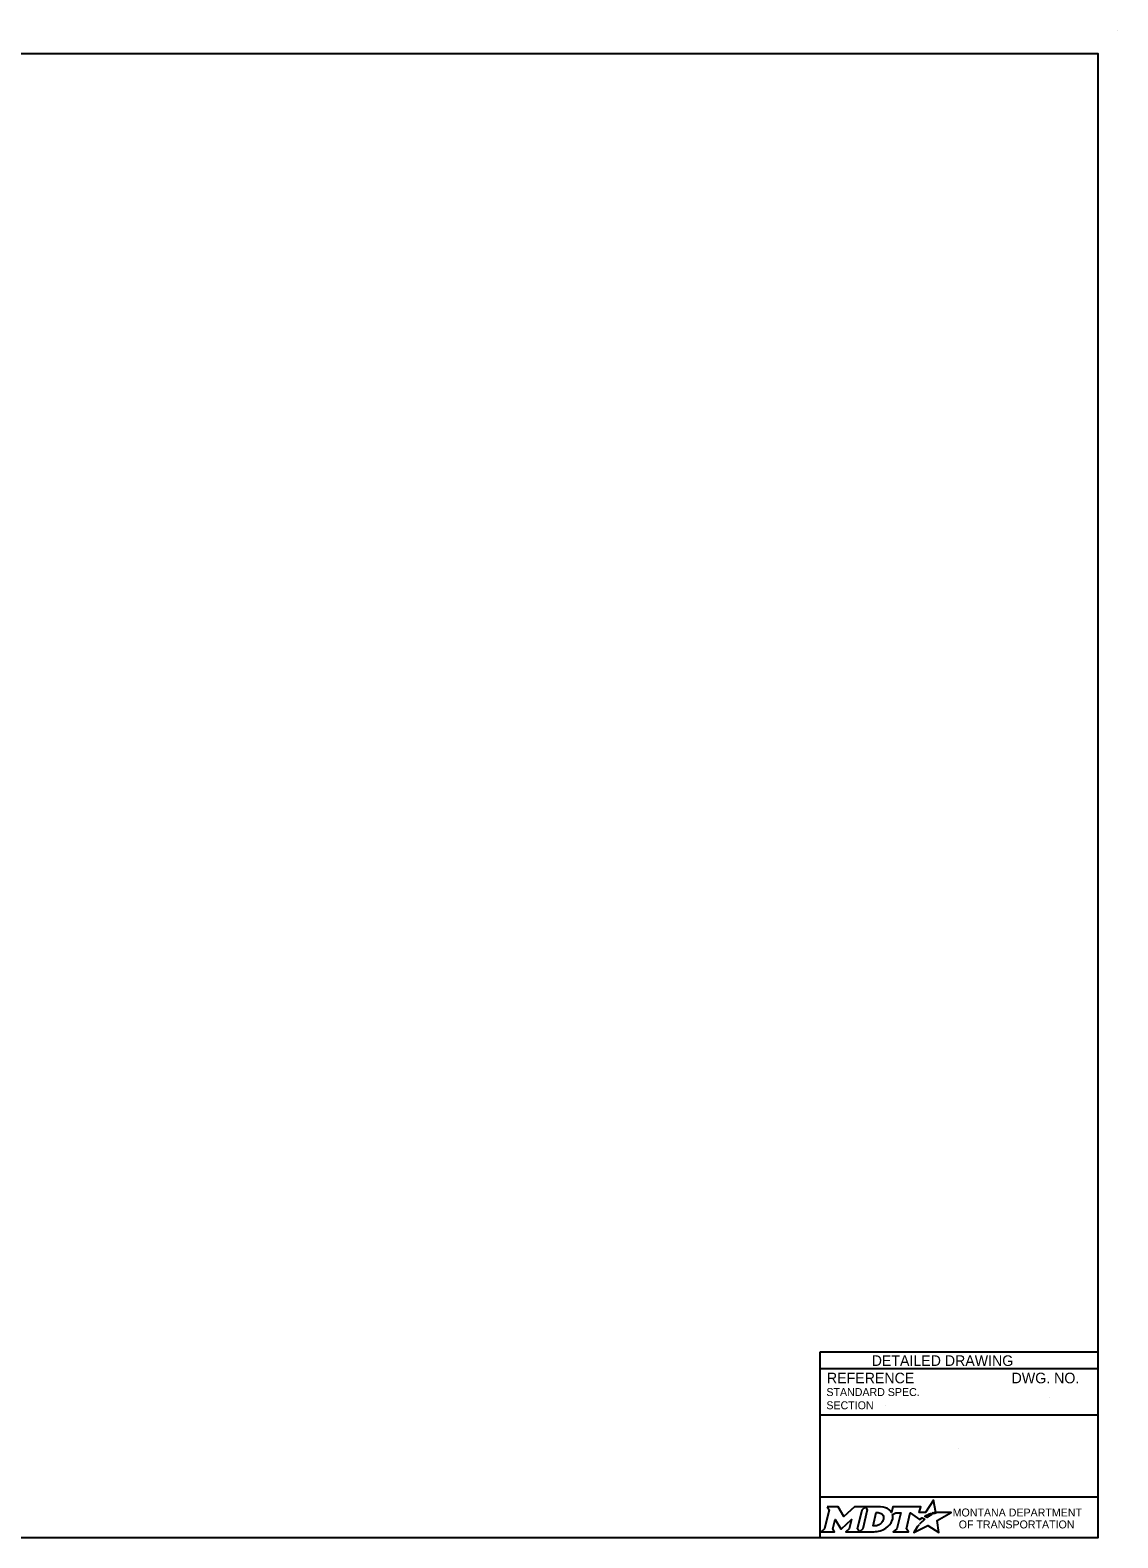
# Model space of a CAD drawing. Extents: x 49991.4 to 50044.5, y 49987.6 to 50011.4.
# Drawn here: x 50008.69 to 50016.9, y 49987.8 to 49999.18 of the extents above; entities that cross this region are included whole.
import ezdxf

# ---------------------------------------------------------------- set-up
doc = ezdxf.new("R2010")
doc.units = 0
for name, color, linetype in [('Default', 7, 'Continuous'), ('Level 1', 7, 'Continuous'), ('Level 5', 7, 'Continuous')]:
    doc.layers.add(name, color=color, linetype=linetype)

msp = doc.modelspace()

# ---------------------------------------------------------------- linework, layer by layer
at = {"layer": 'Default'}
for points in [[(50015.513, 49987.981), (50015.502, 49987.987), (50015.514, 49987.99), (50015.526, 49987.991), (50015.508, 49988.082), (50015.449, 49987.99), (50015.401, 49987.99), (50015.412, 49988.034), (50015.202, 49988.034), (50015.192, 49987.991), (50015.186, 49988)], [(50014.706, 49988.034), (50014.72, 49988.01), (50014.686, 49987.867), (50014.66, 49987.845), (50014.762, 49987.845), (50014.749, 49987.867), (50014.765, 49987.937), (50014.809, 49987.868), (50014.814, 49987.868), (50014.889, 49987.938), (50014.872, 49987.867), (50014.848, 49987.845), (50014.949, 49987.845), (50014.936, 49987.868), (50014.969, 49988.011)], [(50014.969, 49988.011), (50014.994, 49988.034), (50014.912, 49988.034), (50014.832, 49987.961), (50014.788, 49988.034), (50014.706, 49988.034)], [(50015.108, 49988.034), (50014.994, 49988.034), (50015.009, 49988.011), (50014.975, 49987.867), (50014.949, 49987.845), (50015.06, 49987.845)], [(50015.132, 49987.947), (50015.13, 49987.939), (50015.127, 49987.93), (50015.123, 49987.922), (50015.118, 49987.914), (50015.111, 49987.907), (50015.103, 49987.901), (50015.095, 49987.896), (50015.086, 49987.892), (50015.077, 49987.89), (50015.067, 49987.889), (50015.052, 49987.889), (50015.075, 49987.989), (50015.091, 49987.989), (50015.099, 49987.988), (50015.106, 49987.986), (50015.113, 49987.983), (50015.119, 49987.979), (50015.124, 49987.974), (50015.128, 49987.968), (50015.13, 49987.962), (50015.132, 49987.955), (50015.132, 49987.952), (50015.132, 49987.947)], [(50015.199, 49987.975), (50015.224, 49987.988), (50015.261, 49987.988), (50015.232, 49987.867), (50015.205, 49987.845), (50015.321, 49987.845), (50015.304, 49987.867), (50015.332, 49987.988), (50015.403, 49987.936), (50015.424, 49987.951), (50015.444, 49987.94)], [(50015.388, 49987.884), (50015.373, 49987.86), (50015.368, 49987.852), (50015.362, 49987.844), (50015.36, 49987.839), (50015.465, 49987.893), (50015.549, 49987.838), (50015.536, 49987.93), (50015.643, 49987.989), (50015.594, 49987.989), (50015.564, 49987.99), (50015.543, 49987.99), (50015.536, 49987.989), (50015.531, 49987.987), (50015.523, 49987.985), (50015.513, 49987.981)], [(50015.462, 49987.954), (50015.46, 49987.952), (50015.442, 49987.961), (50015.452, 49987.967), (50015.456, 49987.969), (50015.465, 49987.973), (50015.47, 49987.976), (50015.478, 49987.979), (50015.485, 49987.982), (50015.497, 49987.974), (50015.493, 49987.972), (50015.489, 49987.97), (50015.484, 49987.967), (50015.479, 49987.965), (50015.478, 49987.963), (50015.475, 49987.962), (50015.472, 49987.96), (50015.47, 49987.959), (50015.467, 49987.957), (50015.465, 49987.955), (50015.462, 49987.954)], [(50015.106, 49987.852), (50015.114, 49987.855), (50015.127, 49987.86), (50015.148, 49987.871)], [(50015.402, 49987.9), (50015.402, 49987.9)]]:
    msp.add_lwpolyline(points, dxfattribs=at)
for centre, radius, start, end in [((50015.087, 49987.973), 0.118, 300.9103, 339.1383), ((50015.131, 49987.955), 0.0709, 339.5329, 15.8582)]:
    msp.add_arc(centre, radius, start, end, dxfattribs=at)
for centre, major_axis, ratio, start_param, end_param in [((50015.106, 49987.986), (0.0834, -0.0037), 0.568097, 0.61298, 1.570796), ((50015.161, 49987.994), (0.0361, -0.0295), 0.469099, 1.225588, 1.570796), ((50015.433, 49987.93), (-0.0112, -0.0097), 0.021651, 3.157348, 6.283185), ((50015.06, 49987.993), (0, 0.148), 0.987302, 3.139398, 3.456847), ((50015.395, 49987.892), (-0.00694, -0.00806), 0.008222, 0, 3.137361), ((50015.412, 49987.911), (-0.0098, -0.0102), 0.016458, 3.141593, 6.279097)]:
    msp.add_ellipse(centre, major_axis=major_axis, ratio=ratio, start_param=start_param, end_param=end_param, dxfattribs=at)
at = {"layer": 'Level 1'}
msp.add_line((50016.9, 49999.176), (50016.9, 49999.176), dxfattribs=at)
msp.add_lwpolyline([(49999.384, 49998.999), (50016.75, 49998.999), (50016.75, 49987.799), (49999.384, 49987.799)], close=True, dxfattribs=at)
at = {"layer": 'Level 5'}
for p, q in [((50016.75, 49989.199), (50014.65, 49989.199)), ((50014.65, 49989.199), (50014.65, 49987.799)), ((50016.75, 49989.074), (50014.65, 49989.074)), ((50016.386, 49988.859), (50016.386, 49988.859)), ((50016.75, 49988.724), (50014.65, 49988.724)), ((50015.144, 49988.799), (50015.144, 49988.799)), ((50015.7, 49988.475), (50015.7, 49988.475)), ((50016.75, 49988.106), (50014.65, 49988.106))]:
    msp.add_line(p, q, dxfattribs=at)

# ---------------------------------------------------------------- texts
at = {"layer": 'Default'}
for s, p in [('MONTANA DEPARTMENT', (50015.653, 49987.96)), ('OF TRANSPORTATION', (50015.699, 49987.87))]:
    msp.add_text(s, height=0.06, rotation=360, dxfattribs=at).set_placement(p)
at = {"layer": 'Level 5'}
for s, height, p in [('DETAILED DRAWING', 0.0799, (50015.042, 49989.096)), ('REFERENCE', 0.08, (50014.704, 49988.965)), ('DWG. NO.', 0.08, (50016.098, 49988.965)), ('STANDARD SPEC.', 0.06, (50014.7, 49988.869)), ('SECTION', 0.06, (50014.7, 49988.769))]:
    msp.add_text(s, height=height, dxfattribs=at).set_placement(p)

doc.saveas('drawing.dxf')
